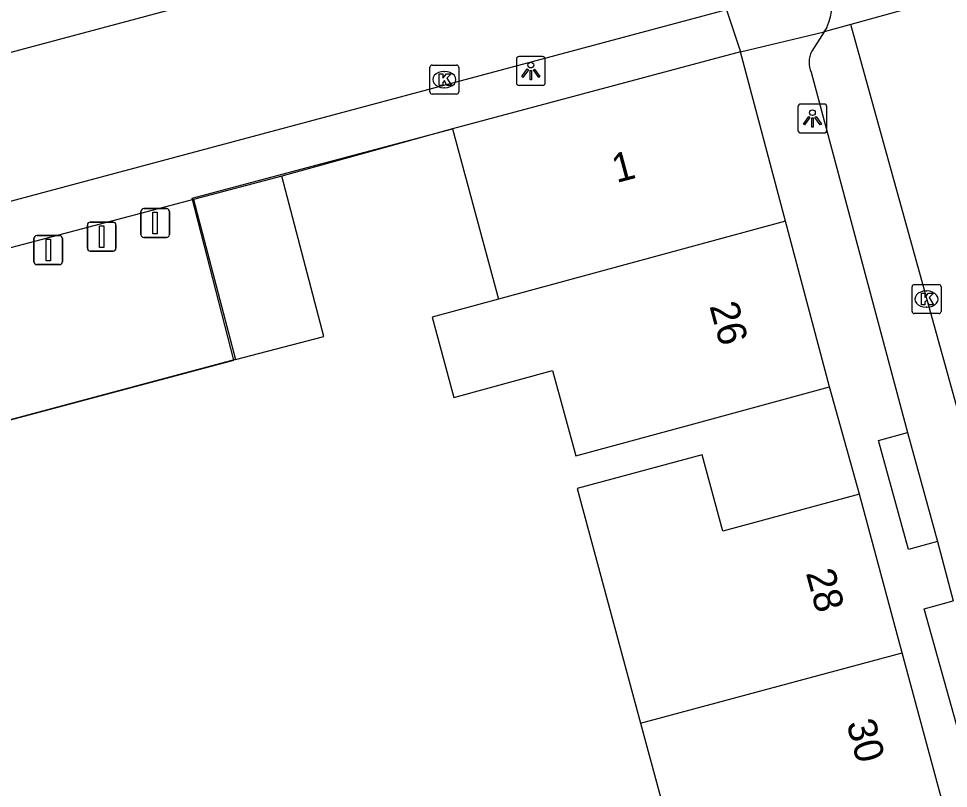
# Model space of a CAD drawing. Extents: x 159265 to 160143, y 383413 to 384319.
# Drawn here: x 159644.66 to 159676.81, y 383618.26 to 383644.88 of the extents above; entities that cross this region are included whole.
import ezdxf

# ---------------------------------------------------------------- set-up
doc = ezdxf.new("R2010")
doc.units = 0
for name, color, linetype in [('IMGEO_Afsluitpaal', 7, 'Continuous'), ('IMGEO_Kolk', 7, 'Continuous'), ('IMGEO_Lichtpunt', 7, 'Continuous'), ('IMGEO_Muur', 7, 'Continuous'), ('IMGEO_Pand', 7, 'Continuous'), ('IMGEO_Pand_nummerreeks', 7, 'Continuous'), ('IMGEO_Parkeervlak_open', 7, 'Continuous'), ('IMGEO_Rijbaan_lokaal_open', 7, 'Continuous'), ('IMGEO_Voetpad_open', 7, 'Continuous')]:
    doc.layers.add(name, color=color, linetype=linetype)

msp = doc.modelspace()

# ---------------------------------------------------------------- linework, layer by layer
at = {"layer": 'IMGEO_Afsluitpaal'}
for p, q in [((159648.883, 383637.412), (159648.883, 383638.212)), ((159648.883, 383638.212), (159648.883, 383637.412)), ((159648.983, 383638.312), (159649.773, 383638.312)), ((159649.773, 383638.312), (159648.983, 383638.312)), ((159649.873, 383638.212), (159649.873, 383637.412)), ((159649.873, 383637.412), (159649.873, 383638.212)), ((159647.134, 383637.844), (159647.924, 383637.844)), ((159647.924, 383637.844), (159647.134, 383637.844)), ((159647.034, 383636.944), (159647.034, 383637.744)), ((159647.034, 383637.744), (159647.034, 383636.944)), ((159648.024, 383637.744), (159648.024, 383636.944)), ((159648.024, 383636.944), (159648.024, 383637.744)), ((159645.185, 383636.476), (159645.185, 383637.276)), ((159645.185, 383637.276), (159645.185, 383636.476)), ((159645.285, 383637.376), (159646.075, 383637.376)), ((159646.075, 383637.376), (159645.285, 383637.376)), ((159646.175, 383637.276), (159646.175, 383636.476)), ((159646.175, 383636.476), (159646.175, 383637.276)), ((159649.773, 383637.312), (159648.983, 383637.312)), ((159648.983, 383637.312), (159649.773, 383637.312)), ((159647.924, 383636.844), (159647.134, 383636.844)), ((159647.134, 383636.844), (159647.924, 383636.844)), ((159646.075, 383636.376), (159645.285, 383636.376)), ((159645.285, 383636.376), (159646.075, 383636.376))]:
    msp.add_line(p, q, dxfattribs=at)
for points in [[(159649.303, 383638.187), (159649.453, 383638.187), (159649.453, 383637.437), (159649.303, 383637.437), (159649.303, 383638.187)], [(159647.454, 383637.719), (159647.604, 383637.719), (159647.604, 383636.969), (159647.454, 383636.969), (159647.454, 383637.719)], [(159645.605, 383637.251), (159645.755, 383637.251), (159645.755, 383636.501), (159645.605, 383636.501), (159645.605, 383637.251)]]:
    msp.add_lwpolyline(points, dxfattribs=at)
for centre, start, end in [((159648.983, 383638.212), 90, 180), ((159648.983, 383638.212), 90, 180), ((159649.773, 383638.212), 0, 90), ((159649.773, 383638.212), 360, 90), ((159647.134, 383637.744), 90, 180), ((159647.134, 383637.744), 90, 180), ((159647.924, 383637.744), 0, 90), ((159647.924, 383637.744), 360, 90), ((159645.285, 383637.276), 90, 180), ((159645.285, 383637.276), 90, 180), ((159646.075, 383637.276), 0, 90), ((159646.075, 383637.276), 360, 90), ((159648.983, 383637.412), 180, 270), ((159648.983, 383637.412), 180, 270), ((159649.773, 383637.412), 270, 0), ((159649.773, 383637.412), 270, 0), ((159647.134, 383636.944), 180, 270), ((159647.134, 383636.944), 180, 270), ((159647.924, 383636.944), 270, 0), ((159647.924, 383636.944), 270, 0), ((159645.285, 383636.476), 180, 270), ((159645.285, 383636.476), 180, 270), ((159646.075, 383636.476), 270, 0), ((159646.075, 383636.476), 270, 0)]:
    msp.add_arc(centre, 0.1, start, end, dxfattribs=at)
at = {"layer": 'IMGEO_Kolk'}
for p, q in [((159658.951, 383643.273), (159659.803, 383643.273)), ((159658.876, 383642.347), (159658.876, 383643.199)), ((159659.364, 383643.053), (159659.389, 383643.053)), ((159659.877, 383643.199), (159659.877, 383642.347)), ((159659.803, 383642.273), (159658.951, 383642.273)), ((159659.387, 383642.493), (159659.362, 383642.493)), ((159675.55, 383634.757), (159675.55, 383635.609)), ((159675.625, 383635.683), (159676.477, 383635.683)), ((159676.551, 383635.609), (159676.551, 383634.757)), ((159676.038, 383635.463), (159676.063, 383635.463)), ((159676.061, 383634.903), (159676.036, 383634.903)), ((159676.477, 383634.683), (159675.625, 383634.683))]:
    msp.add_line(p, q, dxfattribs=at)
for points in [[(159658.951, 383643.273), (159659.803, 383643.273)], [(159658.876, 383642.347), (159658.876, 383643.199)], [(159659.197, 383642.973), (159659.32, 383642.973), (159659.32, 383642.822), (159659.45, 383642.973), (159659.614, 383642.973), (159659.468, 383642.822), (159659.621, 383642.573), (159659.469, 383642.573), (159659.384, 383642.737), (159659.32, 383642.67), (159659.32, 383642.573), (159659.197, 383642.573), (159659.197, 383642.973)], [(159659.877, 383643.199), (159659.877, 383642.347)], [(159659.803, 383642.273), (159658.951, 383642.273)], [(159675.55, 383634.757), (159675.55, 383635.609)], [(159675.625, 383635.683), (159676.477, 383635.683)], [(159676.551, 383635.609), (159676.551, 383634.757)], [(159675.871, 383635.383), (159675.994, 383635.383), (159675.994, 383635.232), (159676.124, 383635.383), (159676.288, 383635.383), (159676.142, 383635.232), (159676.295, 383634.983), (159676.143, 383634.983), (159676.058, 383635.147), (159675.994, 383635.08), (159675.994, 383634.983), (159675.871, 383634.983), (159675.871, 383635.383)], [(159676.477, 383634.683), (159675.625, 383634.683)]]:
    msp.add_lwpolyline(points, dxfattribs=at)
for centre, start, end in [((159658.953, 383643.197), 91.552, 178.448), ((159658.953, 383643.197), 91.552, 178.448), ((159659.801, 383643.197), 1.552, 88.448), ((159659.801, 383643.197), 1.552, 88.448), ((159658.953, 383642.349), 181.552, 268.448), ((159658.953, 383642.349), 181.552, 268.448), ((159659.801, 383642.349), 271.552, 358.448), ((159659.801, 383642.349), 271.552, 358.448), ((159675.627, 383635.607), 91.552, 178.448), ((159675.627, 383635.607), 91.552, 178.448), ((159676.475, 383635.607), 1.552, 88.448), ((159676.475, 383635.607), 1.552, 88.448), ((159675.627, 383634.759), 181.552, 268.448), ((159675.627, 383634.759), 181.552, 268.448), ((159676.475, 383634.759), 271.552, 358.448), ((159676.475, 383634.759), 271.552, 358.448)]:
    msp.add_arc(centre, 0.0765, start, end, dxfattribs=at)
for centre, major_axis, ratio, start_param, end_param in [((159659.363, 383642.773), (-0.387, 0.002), 0.722429, 4.712389, 7.853982), ((159659.388, 383642.773), (-0.39, 0.002), 0.717154, 1.570796, 4.712389), ((159676.037, 383635.183), (-0.387, 0.002), 0.722429, 4.712389, 7.853982), ((159676.062, 383635.183), (-0.39, 0.002), 0.717154, 1.570796, 4.712389)]:
    msp.add_ellipse(centre, major_axis=major_axis, ratio=ratio, start_param=start_param, end_param=end_param, dxfattribs=at)
at = {"layer": 'IMGEO_Lichtpunt'}
for p, q in [((159662.771, 383643.571), (159661.963, 383643.571)), ((159662.771, 383643.571), (159661.963, 383643.571)), ((159661.869, 383643.476), (159661.869, 383642.669)), ((159661.869, 383643.476), (159661.869, 383642.669)), ((159662.865, 383642.669), (159662.865, 383643.476)), ((159662.865, 383642.669), (159662.865, 383643.476)), ((159661.963, 383642.575), (159662.771, 383642.575)), ((159661.963, 383642.575), (159662.771, 383642.575)), ((159671.606, 383641.831), (159671.606, 383641.024)), ((159671.606, 383641.831), (159671.606, 383641.024)), ((159672.508, 383641.926), (159671.7, 383641.926)), ((159672.508, 383641.926), (159671.7, 383641.926)), ((159672.602, 383641.024), (159672.602, 383641.831)), ((159672.602, 383641.024), (159672.602, 383641.831)), ((159671.7, 383640.93), (159672.508, 383640.93)), ((159671.7, 383640.93), (159672.508, 383640.93))]:
    msp.add_line(p, q, dxfattribs=at)
for points in [[(159662.243, 383643.14), (159662.282, 383643.112), (159662.094, 383642.85), (159662.056, 383642.877), (159662.243, 383643.14)], [(159662.345, 383643.092), (159662.392, 383643.092), (159662.392, 383642.77), (159662.345, 383642.77), (159662.345, 383643.092)], [(159662.455, 383643.112), (159662.493, 383643.139), (159662.68, 383642.877), (159662.641, 383642.849), (159662.455, 383643.112)], [(159671.98, 383641.495), (159672.019, 383641.467), (159671.831, 383641.205), (159671.793, 383641.232), (159671.98, 383641.495)], [(159672.082, 383641.447), (159672.129, 383641.447), (159672.129, 383641.125), (159672.082, 383641.125), (159672.082, 383641.447)], [(159672.192, 383641.467), (159672.23, 383641.494), (159672.417, 383641.232), (159672.378, 383641.204), (159672.192, 383641.467)]]:
    msp.add_lwpolyline(points, dxfattribs=at)
for centre in [(159662.368, 383643.274), (159672.105, 383641.629)]:
    msp.add_circle(centre, 0.0994, dxfattribs=at)
for centre, start, end in [((159661.963, 383643.476), 90, 180), ((159661.963, 383643.476), 90, 180), ((159662.771, 383643.476), 0, 90), ((159662.771, 383643.476), 0, 90), ((159661.963, 383642.669), 180, 270), ((159661.963, 383642.669), 180, 270), ((159662.771, 383642.669), 270, 0), ((159662.771, 383642.669), 270, 360), ((159671.7, 383641.831), 90, 180), ((159671.7, 383641.831), 90, 180), ((159672.508, 383641.831), 0, 90), ((159672.508, 383641.831), 0, 90), ((159671.7, 383641.024), 180, 270), ((159671.7, 383641.024), 180, 270), ((159672.508, 383641.024), 270, 0), ((159672.508, 383641.024), 270, 360)]:
    msp.add_arc(centre, 0.0946, start, end, dxfattribs=at)
at = {"layer": 'IMGEO_Muur'}
for points in [[(159653.775, 383639.502), (159659.655, 383641.071)], [(159650.657, 383638.67), (159653.775, 383639.502)], [(159652.094, 383633.067), (159650.657, 383638.67)], [(159639.792, 383629.783), (159652.094, 383633.067)]]:
    msp.add_lwpolyline(points, dxfattribs=at)
at = {"layer": 'IMGEO_Pand'}
for points in [[(159669.621, 383643.735), (159659.655, 383641.071)], [(159671.177, 383637.876), (159669.621, 383643.735)], [(159659.655, 383641.071), (159661.254, 383635.18)], [(159653.76, 383639.43), (159650.705, 383638.63)], [(159652.155, 383633.094), (159655.21, 383633.894), (159653.76, 383639.43)], [(159650.705, 383638.63), (159652.155, 383633.094)], [(159671.177, 383637.876), (159661.254, 383635.18)], [(159672.697, 383632.15), (159671.177, 383637.876)], [(159661.254, 383635.18), (159658.951, 383634.554), (159659.705, 383631.782), (159663.119, 383632.71), (159663.919, 383629.765), (159667.872, 383630.839), (159672.697, 383632.15)], [(159673.729, 383628.433), (159669.009, 383627.153), (159668.287, 383629.796), (159663.973, 383628.628), (159666.165, 383620.512)], [(159675.208, 383622.953), (159673.729, 383628.433)], [(159666.165, 383620.512), (159675.208, 383622.953)], [(159676.687, 383617.473), (159676.571, 383617.906), (159675.208, 383622.953)], [(159666.165, 383620.512), (159667.644, 383615.032), (159676.687, 383617.473)]]:
    msp.add_lwpolyline(points, dxfattribs=at)
at = {"layer": 'IMGEO_Parkeervlak_open'}
msp.add_lwpolyline([(159652.155, 383633.094), (159639.792, 383629.783)], dxfattribs=at)
at = {"layer": 'IMGEO_Rijbaan_lokaal_open'}
for points in [[(159631.622, 383640.314), (159667.815, 383649.99)], [(159677.362, 383645.771), (159673.428, 383644.681)], [(159669.137, 383645.181), (159621.563, 383632.459)], [(159673.428, 383644.681), (159672.51, 383644.421)], [(159672.51, 383644.421), (159672.609, 383644.575)], [(159688.04, 383597.458), (159681.837, 383614.368), (159673.428, 383644.681)]]:
    msp.add_lwpolyline(points, dxfattribs=at)
msp.add_arc((159670.288, 383645.549), 2.517, 337.2296, 12.4497, dxfattribs=at)
at = {"layer": 'IMGEO_Voetpad_open'}
for points in [[(159669.137, 383645.181), (159669.621, 383643.735)], [(159669.621, 383643.735), (159672.51, 383644.421)], [(159672.51, 383644.421), (159672.08, 383643.752)], [(159672.064, 383643.028), (159675.397, 383630.563)], [(159659.655, 383641.071), (159653.76, 383639.43)], [(159650.705, 383638.63), (159638.302, 383635.358)], [(159673.729, 383628.433), (159672.697, 383632.15)], [(159676.427, 383626.797), (159675.424, 383626.523), (159674.394, 383630.289), (159675.397, 383630.563)], [(159675.397, 383630.563), (159676.427, 383626.797)], [(159676.427, 383626.797), (159676.974, 383624.745)], [(159678.621, 383618.855), (159677.619, 383618.575), (159675.972, 383624.465), (159676.974, 383624.745)]]:
    msp.add_lwpolyline(points, dxfattribs=at)
msp.add_arc((159672.83, 383643.373), 0.84, 153.2063, 204.2617, dxfattribs=at)

# ---------------------------------------------------------------- texts
at = {"layer": 'IMGEO_Pand_nummerreeks'}
for s, rotation, p in [('1', 14.9669, (159665.329, 383639.192)), ('26', 285.1974, (159668.539, 383634.946)), ('28', 285.1087, (159671.874, 383625.713)), ('30', 285.1087, (159673.277, 383620.514))]:
    msp.add_text(s, height=1, rotation=rotation, dxfattribs=at).set_placement(p)

doc.saveas('drawing.dxf')
